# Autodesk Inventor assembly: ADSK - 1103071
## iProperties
Created: 2007-03
Part Number: ADSK - 1103071
Description: 2 SHOE FLYWHEEL
Document SubType Name: Assembly
Designer: garnert
Mass: 8.46348 g
Surface Area: 28.0302 cm^2
Volume: 3.12305 cm^3
Density: 2.71 g/cm^3
Author: garnert
